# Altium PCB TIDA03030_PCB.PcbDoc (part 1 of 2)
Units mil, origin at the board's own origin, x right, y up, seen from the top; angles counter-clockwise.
Board outline 2230 x 2185 mil, 4 copper layers (Top Layer, Power, Gnd, Bottom Layer), stack 59.6 mil thick; 88 components, 48 nets, 250 pads, 119 vias.
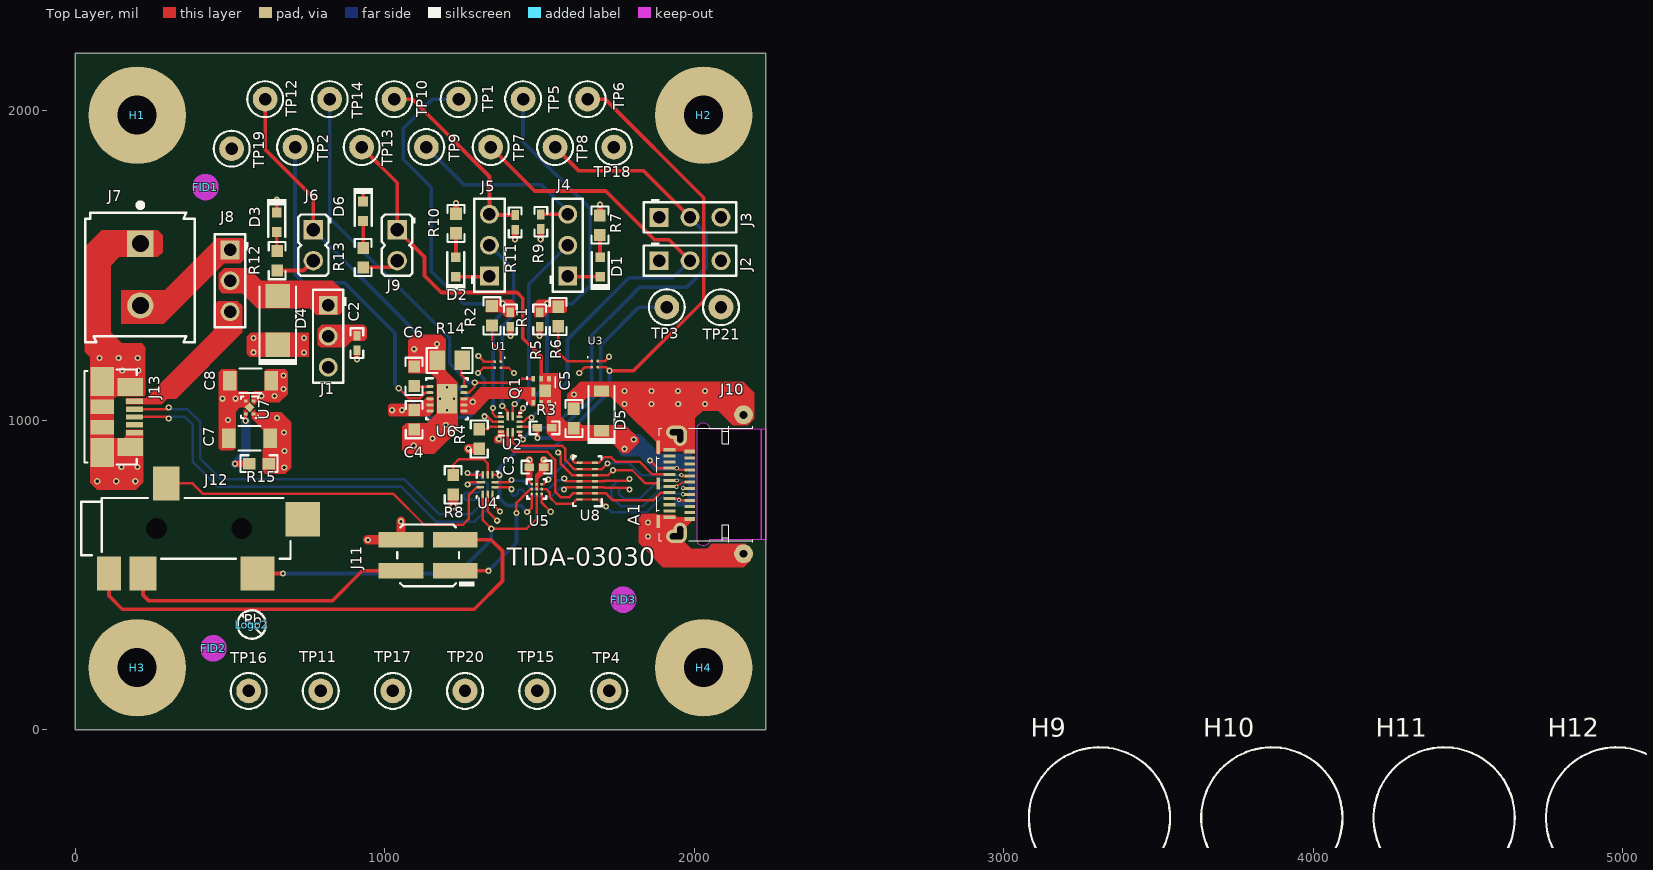
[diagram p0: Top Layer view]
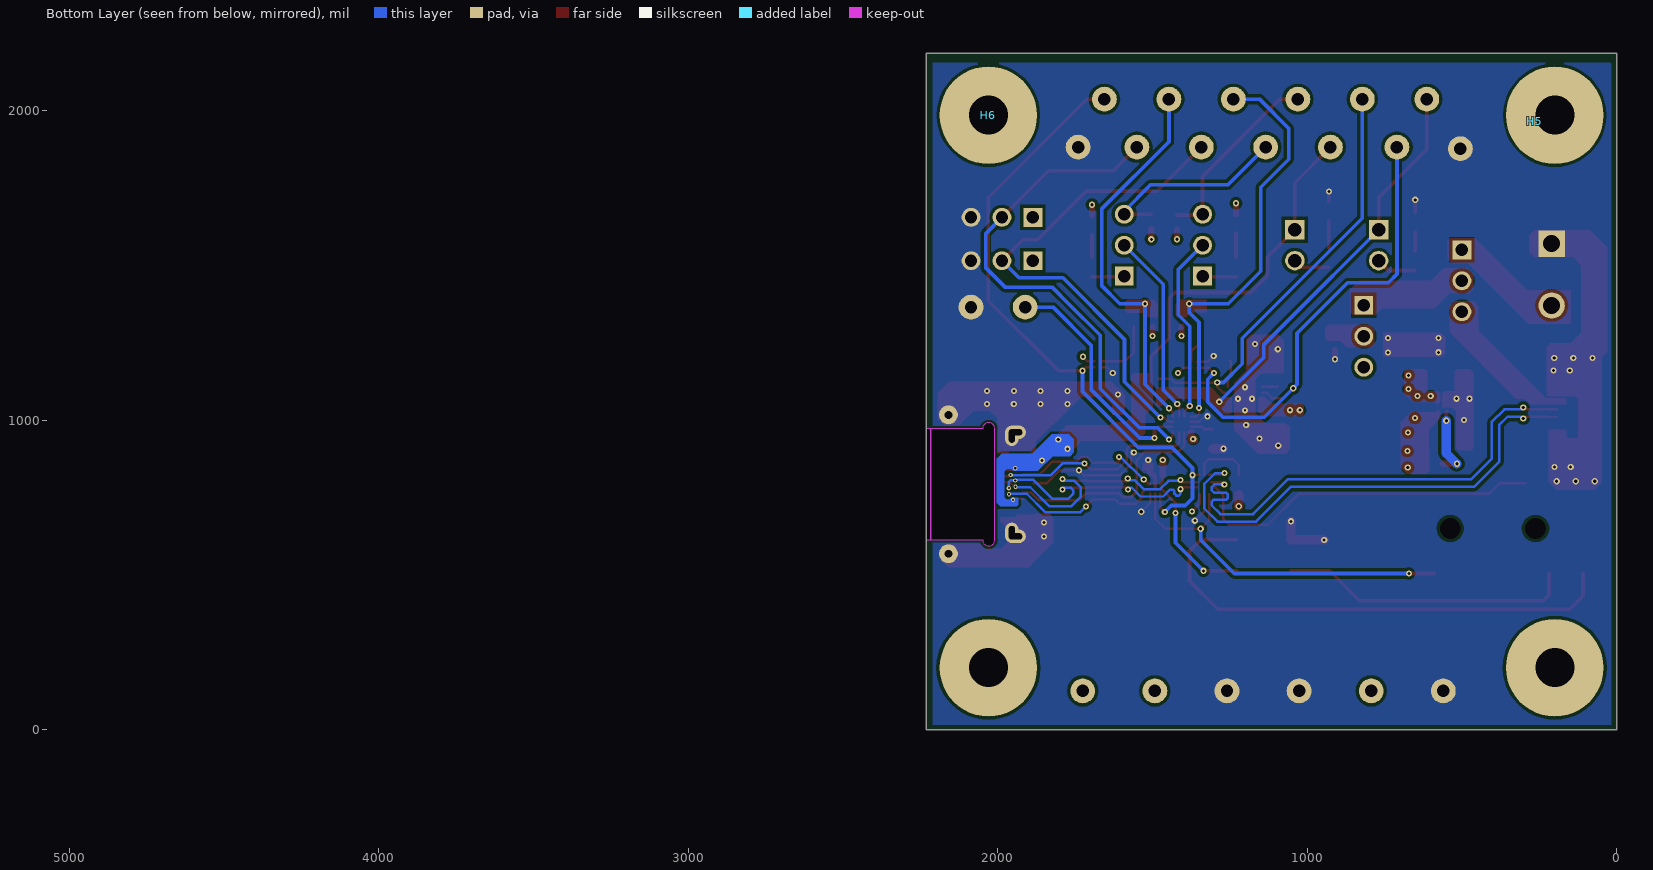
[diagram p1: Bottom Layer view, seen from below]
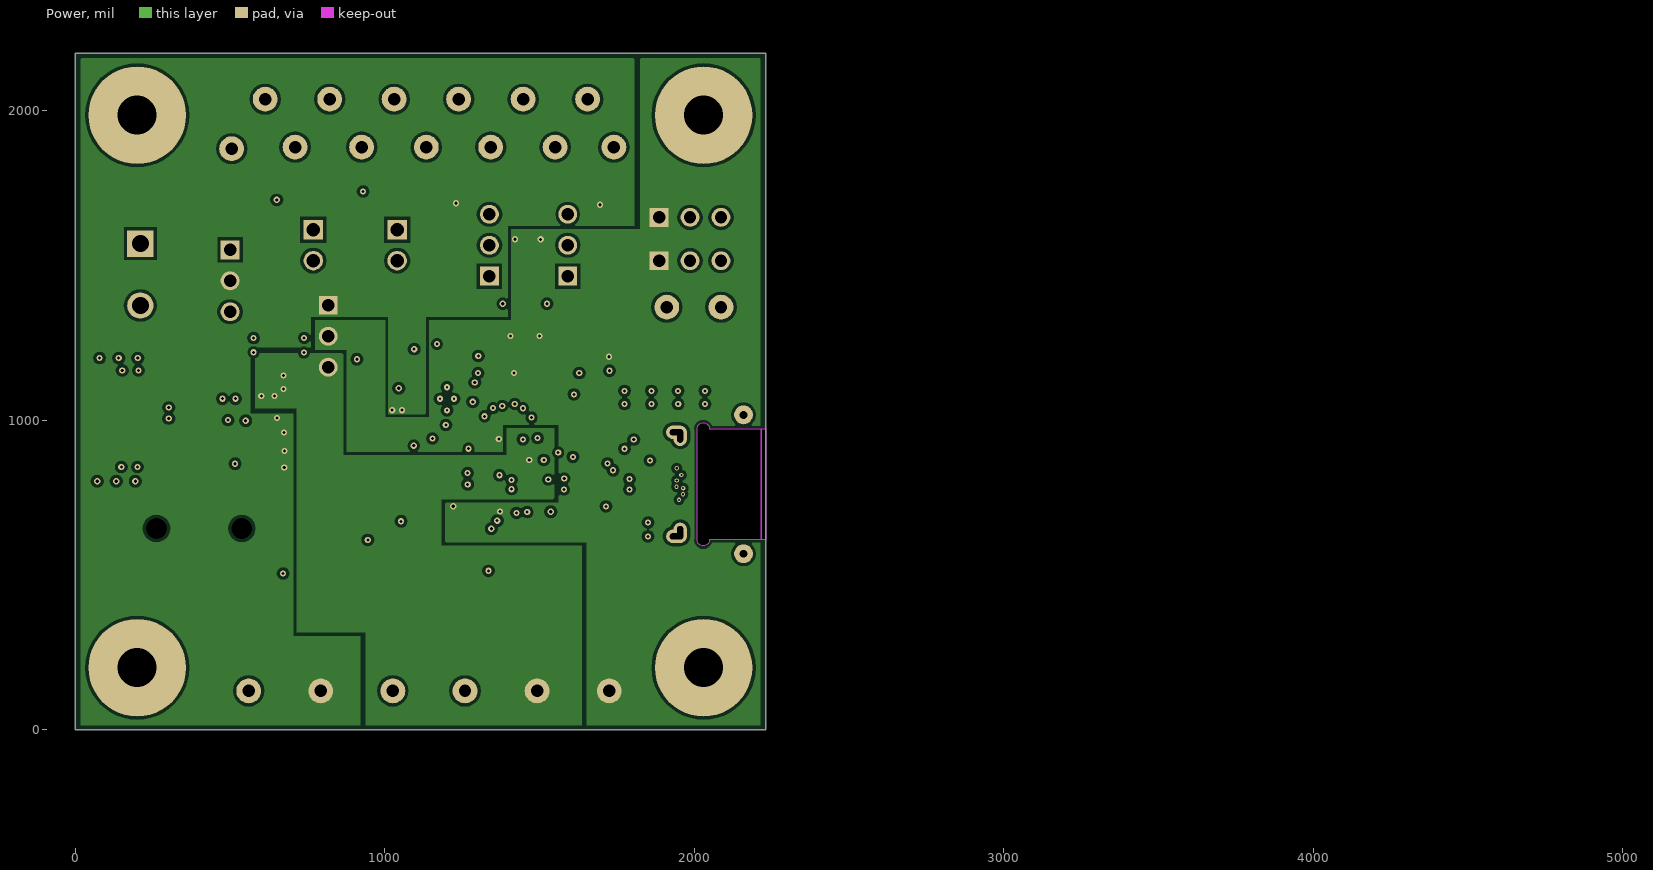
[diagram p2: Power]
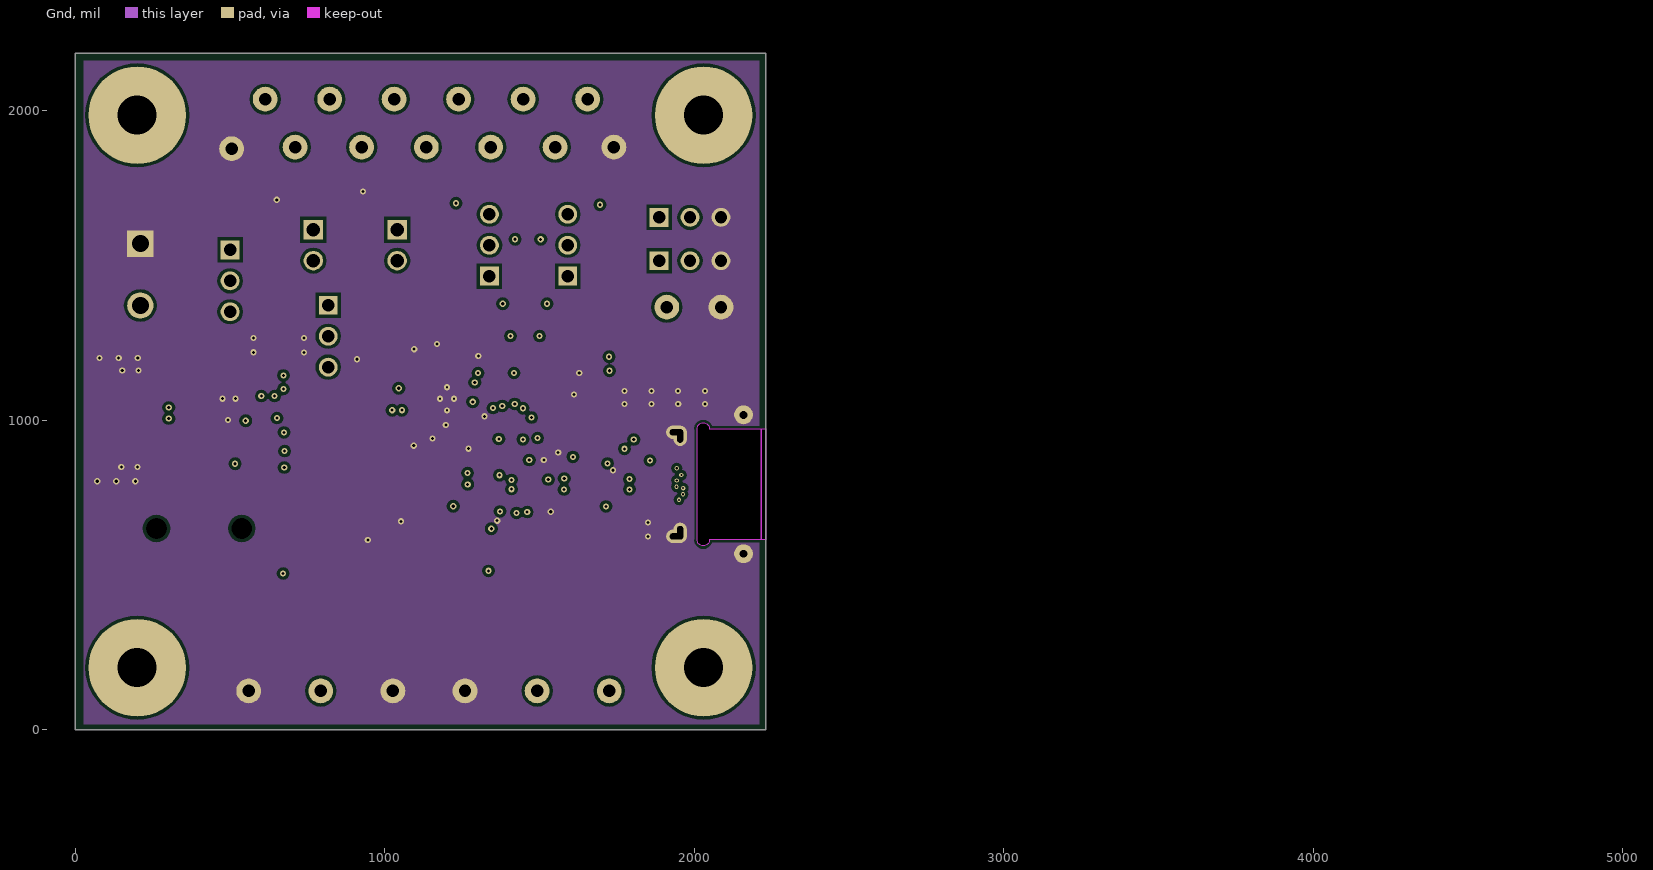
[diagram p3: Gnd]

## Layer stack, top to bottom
Top Solder: solder mask 0.7, Solder Resist, Dk 3.5
Top Layer: signal copper 1.5
Dielectric1: core 6, FR-4, Dk 4.8
Power: signal copper 1.3
Dielectric 2: core 42, Dk 4.2
Gnd: signal copper 1.3
Dielectric 3: core 6, Dk 4.2
Bottom Layer: signal copper 1.5
Bottom Solder: solder mask 0.7, Solder Resist, Dk 3.5

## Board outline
0,0 2230,0 2230,2185 0,2185
cut-out: 2215.86,971.64 2230,971.64 2230,613.38 2230,613.37 2215.86,613.37

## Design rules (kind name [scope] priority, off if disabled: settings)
AcuteAngle [All] p1: minimum=4.50000000000000E+0001 checktracksonly=FALSE
AssemblyTestPointUsage [All] p1: valid=2
Clearance Clearance_1 [withinroom('RoomDefinition_1')] p1: gap=5
Clearance Clearance_Keepouts [((IsTrack Or IsArc) And Not InPoly) And IsFree and IsKeepOut vs ((IsTrack Or IsArc) And Not InPoly) And IsFree and IsKeepOut] p2: gap=0
Clearance Clearance_Poly [InPolygon] p3: gap=10
Clearance [All] p4: gap=5
ComponentClearance ComponentClearance_MountingHoles_FiducialMarks [InComponentClass('Mounting Holes') vs InComponentClass('FiducialMark')] p1: gap=50 collisioncheckmode=3 verticalgap=10 showdistances=FALSE
ComponentClearance ComponentClearance_Shunt [InComponentClass('Header') vs InComponentClass('Shunt')] p2: gap=0 collisioncheckmode=3 verticalgap=0 showdistances=FALSE
ComponentClearance ComponentClearance_Logo [InComponentClass('Logo')] p3: gap=50 collisioncheckmode=3 verticalgap=10 showdistances=FALSE
ComponentClearance ComponentClearance_ScrewToNut [(HasFootprint('NY PMS 440 0025 PH')) vs (HasFootprint('Keystone_1902C'))] p4: gap=5 collisioncheckmode=3 verticalgap=10 showdistances=FALSE
ComponentClearance ComponentClearance_MountingHoles [InComponentClass('Mounting Holes')] p5: gap=250 collisioncheckmode=3 verticalgap=100000 showdistances=FALSE
ComponentClearance ComponentClearance_SmallPassives [HasFootprint('0201*') or HasFootprint('0402*') or HasFootprint('0508') or HasFootprint('0603*') or HasFootprint('0612') or HasFootprint('0805*') or HasFootprint('0815*') or HasFootprint('0830*') or HasFootprint('1206*') or HasFootprint('1210*') or HasFootprint('1808*') or HasFootprint('1812*') or HasFootprint('1825*') or HasFootprint('2010*') or HasFootprint('2220*') or HasFootprint('2225*') or HasFootprint('2512*') or HasFootprint('2728*') or HasFootprint('3518*') vs HasFootprint('0201*') or HasFootprint('0402*') or HasFootprint('0508') or HasFootprint('0603*') or HasFootprint('0612') or HasFootprint('0805*') or HasFootprint('0815*') or HasFootprint('0830*') or HasFootprint('1206*') or HasFootprint('1210*') or HasFootprint('1808*') or HasFootprint('1812*') or HasFootprint('1825*') or HasFootprint('2010*') or HasFootprint('2220*') or HasFootprint('2225*') or HasFootprint('2512*') or HasFootprint('2728*') or HasFootprint('3518*')] p6: gap=14.96 collisioncheckmode=3 verticalgap=10 showdistances=FALSE
ComponentClearance ComponentClearance_THtoSMT [IsThruComponent vs IsSMTComponent] p7: gap=40 collisioncheckmode=3 verticalgap=30 showdistances=FALSE
ComponentClearance ComponentClearance_THtoTH [IsThruComponent vs IsThruComponent] p8: gap=30 collisioncheckmode=3 verticalgap=30 showdistances=FALSE
ComponentClearance [All] p9: gap=30 collisioncheckmode=3 verticalgap=10 showdistances=FALSE
DiffPairsRouting [All] p1: maxlimit=16 minlimit=16 mostfreqgap=16 toplayer_minwidth=6 toplayer_maxwidth=20 toplayer_prefwidth=10 midlayer1_minwidth=6 midlayer1_maxwidth=20 midlayer1_prefwidth=10 midlayer2_minwidth=6 midlayer2_maxwidth=20 midlayer2_prefwidth=10 bottomlayer_minwidth=6 bottomlayer_maxwidth=20 bottomlayer_prefwidth=10 maxuncoupledlength=1000
FabricationTestPointUsage TestPointUsage [All] p1: valid=2 allowmultiple=FALSE
FabricationTestpoint Testpoint [All] p1: side=3 testpointundercomponent=TRUE minsize=40 maxsize=100 preferedsize=60 minholesize=0 maxholesize=40 preferedholesize=32 testpointgrid=1 allowsidetop=TRUE allowsidebottom=TRUE usegrid=TRUE gridtolerance=0.01
FanoutControl Fanout_LCC [IsLCC] p1: bgadir=Out bgaviamode=Centered fanoutstyle=Auto fanoutdirection=Alternating viagrid=1 // Fanout_LCC (Default Rule)
FanoutControl Fanout_BGA [IsBGA] p2: bgadir=Out bgaviamode=Centered fanoutstyle=Auto fanoutdirection=Alternating viagrid=1 // Fanout_BGA (Default Rule)
FanoutControl Fanout_Default [All] p4: bgadir=Out bgaviamode=Centered fanoutstyle=Auto fanoutdirection=Alternating viagrid=1 // Fanout_Default (Default Rule)
FanoutControl Fanout_Small [(CompPinCount < 5)] p5: bgadir=Out bgaviamode=Centered fanoutstyle=Auto fanoutdirection=OutThenIn viagrid=1 // Fanout_Small (Default Rule)
HoleSize [All] p1: absolutevalues=TRUE maxlimit=251 minlimit=7 maxpercent=80.000 minpercent=20.000
MinimumAnnularRing MinimumAnnularRing_ThermalPadVias [IsVia and InAnyComponent] p1: minimumring=5
MinimumAnnularRing [All] p2: minimumring=3
MinimumSolderMaskSliver MinimumSolderMaskSliver_Logo [InComponentClass('Logo') vs InComponentClass('Logo')] p1: minsoldermaskwidth=0.7
MinimumSolderMaskSliver [All] p2: minsoldermaskwidth=3.94
PlaneClearance [All] p1: clearance=10
PlaneConnect [All] p1: planeconnectstyle=Direct reliefexpansion=10 reliefentries=4 reliefconductorwidth=10 reliefairgap=10
PolygonConnect [All] p1: connectstyle=Direct reliefconductorwidth=10 reliefentries=4 polygonreliefangle="90 Angle" airgapwidth=10
RoutingVias ThermalPadVias [IsVia and InAnyComponent] p1: holewidth=7.87 width=19.68 viastyle="Through Hole" minholewidth=7.87 minwidth=19.68 maxholewidth=12.99 maxwidth=23.62
RoutingVias [All] p2: holewidth=16 width=34 viastyle="Through Hole" minholewidth=7 minwidth=14 maxholewidth=10 maxwidth=20
SilkToBoardRegionClearance [Not ((IsComment or IsDesignator) And (Hide <> 'False')) and not InRegion(1000,500,4000,800)] p1:
SilkToSilkClearance SilkToSilkClearance_Pb-FreeLogo [(HasFootprint('Pb-Free_Overlay_Medium') OR HasFootprint('Pb-Free_Overlay_Small')) vs (HasFootprint('Pb-Free_Overlay_Medium') OR HasFootprint('Pb-Free_Overlay_Small'))] p1: silktosilkclearance=0
SilkToSilkClearance [All] p2: silktosilkclearance=4
SilkToSolderMaskClearance SilkToComponentPadClearance [IsPad and InAnycomponent] p1: minsilkscreentomaskgap=5 clearancetoexposedcopper=TRUE
SilkToSolderMaskClearance "Silk to Solder Mask Opening" [All] p2: minsilkscreentomaskgap=4 clearancetoexposedcopper=FALSE
SolderMaskExpansion [All] p1: expansion=1.97
Width [All] p1: maxlimit=30 minlimit=3 preferedwidth=12 toplayer_minwidth=5 toplayer_prefwidth=8 midlayer1_minwidth=8 midlayer2_minwidth=8 minimp=50.000000 maximp=50.000000 favimp=50.000000 checkconnectedcopper=TRUE
14 further rules are at their usual default settings.

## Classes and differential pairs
component class TIDA03030_Controller&Switches: 45 C2 C3 D1 D2 J1 J2 J3 J4 J5 R1 R2 R3 R4 R5 R6 R7 R8 R9 R10 R11 TP1 TP2 TP3 TP4 TP5 TP6 TP7 TP8 TP9 TP10 U1 U2 U3 U4 U5
component class TIDA03030_Hardware: FID1 FID2 FID3 H1 H2 H3 H4 H5 H6 H9 H10 H11 H12 Logo2 Logo3 TIDA-03030
component class FiducialMark: FID1 FID2 FID3
component class Header: J6 J9 J11
component class TIDA03030_Connectors: J10 J11 J12 J13 U8
component class TIDA03030_Power: C4 C5 C6 C7 C8 D3 D4 D5 D6 J6 J7 J8 J9 Q1 R12 R13 R14 R15 TP11 TP12 TP13 TP14 TP15 TP16 TP17 TP18 TP19 TP20 TP21 U6 U7
component class "Mounting Holes": H1 H2 H3 H4
differential pair NewDifferentialPair2: +USB_D+ -USB_D-
differential pair NewDifferentialPair1: +USB_C_D- -USB_C_D+

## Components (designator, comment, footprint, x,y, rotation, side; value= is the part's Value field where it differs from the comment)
C2 "GCM155R71C104KA55D" 0402 910,1249 r270 top
C3 "GCM155R71C104KA55D" 0402 1490,848 r0 top
C4 "GCM188R71C105KA64D" 0603 1094.5,1001.57 r270 top
C5 "GCM188R71C105KA64D" 0603 1611,1005 r90 top
C6 "GRM1885C1H302JA01D" 0603 1094.5,1141.57 r90 top
C7 "C3216X7R1H105K160AB" 1206_180 562.64,941.14 r180 top
C8 "C3216X7R1H105K160AB" 1206_180 566,1127.2 r180 top
D1 "150060GS75000" WL-SMCW_GREEN 1696,1495 r90 top
D2 "150060GS75000" WL-SMCW_GREEN 1229,1495 r90 top
D3 "150060BS75000" WL-SMCW_Blue 651,1639 r270 top
D4 "SMAJ7.5CA" SMA 654,1322 r90 top
D5 "30V" SOD-123 1700,1030 r90 top
D6 "150060BS75000" WL-SMCW_Blue 929.82,1675 r270 top
FID1 "Fiducial" Fiducial10-20#1 420.35,1752.75 r0 top
FID2 "Fiducial" Fiducial10-20#2 494.31,261.44 r0 top
FID3 "Fiducial" Fiducial10-20#1 1770,420 r0 top
H1 "NY PMS 440 0025 PH" "NY PMS 440 0025 PH"#1 265,1965 r0 top
H2 "NY PMS 440 0025 PH" "NY PMS 440 0025 PH"#2 1970,2060 r0 top locked
H3 "NY PMS 440 0025 PH" "NY PMS 440 0025 PH"#3 185,175 r0 top locked
H4 "NY PMS 440 0025 PH" "NY PMS 440 0025 PH"#4 2030,200 r0 top locked
H5 "1902C" Keystone_1902C#1 265,1965 r180 bottom
H6 "1902C" Keystone_1902C#1 2030,1985 r180 bottom
H7 "1902C" Keystone_1902C#2 200,200 r90 bottom
H8 "1902C" Keystone_1902C#2 2030,200 r90 bottom
H9 "SJ-5303 (CLEAR)" Bumpon_SJ5003Transparent 3308.79,-285.01 r90 top
H10 "SJ-5303 (CLEAR)" Bumpon_SJ5003Transparent 3865.61,-285.01 r90 top
H11 "SJ-5303 (CLEAR)" Bumpon_SJ5003Transparent 4422.44,-285.01 r90 top
H12 "SJ-5303 (CLEAR)" Bumpon_SJ5003Transparent 4979.27,-285.01 r90 top
J1 "HTSW-103-09-G-S" Samtec_HTSW-103-09-x-S 817,1271 r270 top
J2 "HTSW-103-09-G-S" Samtec_HTSW-103-09-x-S 1986,1515 r0 top
J3 "HTSW-103-09-G-S" Samtec_HTSW-103-09-x-S 1986,1655 r0 top
J4 "HTSW-103-09-G-S" Samtec_HTSW-103-09-x-S 1591,1565 r90 top
J5 "HTSW-103-09-G-S" Samtec_HTSW-103-09-x-S 1338,1565 r90 top
J6 "961102-6404-AR" 3M_961102-6404-AR 768.82,1565 r270 top
J7 "282841-2" TEC_282841-2 210,1470 r270 top
J8 "HTSW-103-09-G-S" Samtec_HTSW-103-09-x-S 500,1450 r270 top
J9 "961102-6404-AR" 3M_961102-6404-AR 1039.82,1565 r270 top
J10 "20-0000016-01" Lintes_20-0000016-01 2215.86,792.51 r90 top locked
J11 "15-91-2040" Molex_15-91-2040 1140,563 r90 top
J12 "SJ-43515TS-SMT-TR" CUI_SJ-43515TS-SMT 400,650 r0 top locked
J13 "0473460001" CONN_47346-0001 30,1010 r90 top
Logo2 "Pb-Free Symbol" Pb-Free_Overlay_Small 569.93,339.45 r0 top
Q1 "30V" TRANS_NexFET_Q2 1505,1095 r270 top
R1 "CRCW0402200KFKED" 0402 1405.5,1325 r90 top
R2 "CRCW06030000Z0EA" 0603 1346.23,1336.89 r90 top
R3 "CRCW0402909KFKED" 0402 1516,975 r0 top
R4 "CRCW06030000Z0EA" 0603 1305.03,939.17 r90 top
R5 "CRCW0402200KFKED" 0402 1500,1325 r90 top
R6 "CRCW06030000Z0EA" 0603 1560,1335 r90 top
R7 "RC0603FR-07909RL" 0603 1695,1630 r90 top
R8 "CRCW06030000Z0EA" 0603 1221,791 r90 top
R9 "CRCW04024K70JNED" 0402 1504,1641 r270 top
R10 "RC0603FR-07909RL" 0603 1230,1635 r90 top
R11 "CRCW04024K70JNED" 0402 1421,1639 r270 top
R12 "CRCW0603845RFKEA" 0603 652,1515 r270 top
R13 "CRCW0603845RFKEA" 0603 929.82,1525 r270 top
R14 "CRCW080510K2FKEA" 0805_HV 1209.5,1192.57 r0 top
R15 "CRCW06030000Z0EA" 0603 593.36,859.14 r0 top
TIDA-03030 "FCC disclaimer" FCC_disclaimer 2310.5,692.08 r90 top (schematic designator Logo3)
TP1 "5116" Keystone_5116 1238.33,2037 r180 top
TP2 "5116" Keystone_5116 710,1882 r180 top
TP3 "5116" Keystone_5116 1911,1365 r0 top
TP4 "5116" Keystone_5116 1725,125 r180 top
TP5 "5116" Keystone_5116 1446.67,2037 r90 top
TP6 "5116" Keystone_5116 1655,2037 r0 top
TP7 "5116" Keystone_5116 1342,1882 r90 top
TP8 "5116" Keystone_5116 1550,1882 r90 top
TP9 "5116" Keystone_5116 1134,1882 r90 top
TP10 "5116" Keystone_5116 1030,2037 r90 top
TP11 "5117" Keystone5117 793,125 r270 top
TP12 "5117" Keystone5117 613.33,2037 r90 top
TP13 "5117" Keystone5117 925,1882 r90 top
TP14 "5117" Keystone5117 821.67,2037 r180 top
TP15 "5117" Keystone5117 1492,125 r0 top
TP16 "5001" Keystone5001 560,125 r180 top
TP17 "5001" Keystone5001 1026,125 r90 top
TP18 "5001" Keystone5001 1740,1882 r180 top
TP19 "5001" Keystone5001 505,1877 r180 top
TP20 "5001" Keystone5001 1259,125 r180 top
TP21 "5001" Keystone5001 2086,1365 r90 top
U1 "SN74LVC1G04YZVR" YZV0004ADAD 1365,1179 r270 top
U2 "TUSB320LAI" RWB0012A 1405,986.57 r90 top
U3 "SN74LVC1G04YZVR" YZV0004ADAD 1678,1181 r0 top
U4 "TS5USBA224RSWR" RSW0010A 1332,791.57 r0 top
U5 "TS3A226AEYFFR" YFF0009AEAJ 1490.67,777.2 r0 top
U6 "TPS259230DRCR" DRC0010J 1200.76,1068.86 r0 top
U7 "TLV73333PDQNR" DQN0004A 563.2,1041.14 r270 top
U8 "TPD6E05U06RVZR" RVZ0014A 1654,802.57 r180 top

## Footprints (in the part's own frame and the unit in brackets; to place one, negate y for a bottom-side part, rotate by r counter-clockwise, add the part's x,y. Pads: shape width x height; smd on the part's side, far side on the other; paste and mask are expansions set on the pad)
3M_961102-6404-AR [mm] "Header, 2.54mm, 2x1, TH"
  rect 1.6x1.6 hole 1.1: 1(-1.27,0)
  round 1.6 hole 1.1: 2(1.27,0)
  silkscreen extent -2.52,-1.25 2.52,1.5, body extent -2.52,-1.25 2.52,1.25, height 8.5
0402 [mm] "0402 from SM-752 data"
  rect 0.8x0.6 smd: 1(-0.6,0) 2(0.6,0)
  silkscreen extent -1.22,-0.52 1.22,0.52, body extent -0.55,-0.3 0.55,0.3, height 0.6
0603 [mm] "0603 from SM-752 data"
  rect 1x0.95 smd: 1(-0.8,0) 2(0.8,0)
  silkscreen extent -1.52,-0.69 1.52,0.69, body extent -0.87,-0.47 0.87,0.47, height 1
0805_HV [mil] "0805 with 30mil clearance between pads"
  rect 50x63 smd: 1(-40,0) 2(40,0)
  silkscreen extent -74,-40 74,40, body extent -43,-29 43,29, height 57
1206_180 [mm] "1206_180"
  rect 1.1x1.6 smd: 1(-1.7,0) 2(1.7,0)
  silkscreen extent -0.9,-1 0.9,1, body extent -1.75,-0.95 1.75,0.95, height 1.8
Bumpon_SJ5003Transparent [mil] "3M Hemispherical Bumpon transparent"
  round 1 on Mech3: 0(0,0)
  silkscreen extent -228,-228 228,228, body extent -217,-218 219,218, height 197
CONN_47346-0001 [mm] "MOLEX"
  rect 0.45x1.38 smd: 1(1.3,-4.105) 2(0.65,-4.105) 3(0,-4.105) 4(-0.65,-4.105) 5(-1.3,-4.105)
  rect 1.475x2.1 smd: 6(-2.462,-3.755) 11(2.463,-3.75)
  rect 2.375x1.9 smd: 7(-2.912,-1.45) 10(2.912,-1.45)
  rect 1.175x1.9 smd: 8(-0.837,-1.45) 9(0.837,-1.45)
  silkscreen extent -3.9,-4.28 3.9,0, body extent -3.99,-4.43 3.99,1, height 2.72
CUI_SJ-43515TS-SMT [mm] "3.5 mm Audio Jack Connector, Body 17 x 6 mm"
  rect 2x2.8 smd: 1(-7.4,-3.7)
  rect 2.8x2.8 smd: 2(4.8,-3.7) 5(8.5,0.75)
  rect 2.2x2.8 smd: 3(-2.7,3.7) 4(-4.6,-3.7)
  round 1 hole 1.7 unplated mask+0.35: MH1(-3.5,0) MH2(3.5,0)
  silkscreen extent -9.67,-2.5 7.5,2.5, body extent -9.7,-4.5 9.5,4.5, height 5.1
DQN0004A [mm] "SON, 0.65mm pitch"
  rect 0.25x0.31 smd paste-1 mask-0.31: 1(-0.535,0.325) 2(-0.535,-0.325) 3(0.535,-0.325) 4(0.535,0.325)
  rect 0.58x0.58 smd rot 45 paste-0.065 mask+0: 5(0,0)
  Top Layer region: -0.66,0.48 -0.2,0.48 -0.2,0.379 -0.409,0.17 -0.66,0.17
  Top Layer region: 0.66,0.48 0.2,0.48 0.2,0.379 0.409,0.17 0.66,0.17
  Top Layer region: 0.66,-0.48 0.2,-0.48 0.2,-0.379 0.409,-0.17 0.66,-0.17
  Top Layer region: -0.66,-0.48 -0.2,-0.48 -0.2,-0.379 -0.409,-0.17 -0.66,-0.17
  silkscreen extent -0.88,-0.7 0.88,0.7, body extent -0.53,-0.53 0.53,0.53, height 0.42
DRC0010J [mm] "SON, 10-Leads, Body 3x3mm, Pitch 0.5mm, Thermal Pad 2.4x1.65mm, TI Recommended"
  rrect100% 0.6x0.24 smd: 1(-1.4,1) 2(-1.4,0.5) 3(-1.4,0) 4(-1.4,-0.5) 5(-1.4,-1) 6(1.4,-1) 7(1.4,-0.5) 8(1.4,0) 9(1.4,0.5) 10(1.4,1)
  rrect6% 1.65x2.4 smd paste-0.825: 11(0,0)
  silkscreen extent -1.7,-1.7 1.7,1.7, body extent -1.5,-1.5 1.5,1.5, height 0.77
FCC_disclaimer [mil]
Fiducial10-20#1 [mm]
  round 1 smd mask+0.5: 1(0,0)
  Top Layer keep-out circle w1.178: c0,0 r0.5
Fiducial10-20#2 [mm]
  round 1 smd mask+0.5: 1(-1.227,0.03)
  Top Layer keep-out circle w1.178: c-1.227,0.03 r0.5
Keystone5001 [mil] "For Keystone 500x miniature loop terminals"
  round 80 hole 40: 1(0,0)
  silkscreen extent -58,-58 58,58, body extent -49,-49 49,49, height 182
Keystone5117 [mil] "For Keystone 500x miniature loop terminals"
  round 80 hole 40: 1(0,0)
  silkscreen extent -58,-58 58,58, body extent -49,-49 49,49, height 182
Keystone_1902C#1 [mil] "Hex Standoff, 4-40 threaded, nylon"
  body extent -1910,-106 -1620,146, height 501
Keystone_1902C#2 [mil] "Hex Standoff, 4-40 threaded, nylon"
  round 1 on Mech4: 0(0,0)
  body extent -145,-126 146,126, height 501
Keystone_5116 [mil] "For Keystone 500x miniature loop terminals"
  round 80 hole 40: 1(0,0)
  silkscreen extent -58,-58 58,58, body extent -50,-49 50,51, height 183
Lintes_20-0000016-01 [mm] "Connector, Receptacle, USB Type C, SMT"
  rect 1.1x0.3 smd: 1(3.05,8.44) 3(-3.05,8.44)
  rect 1x0.3 smd: 2(0.07,8.44)
  rect 0.3x0.95 smd: A1(-2.7,7.525) A12(2.85,7.525)
  rect 0.25x0.95 smd: A2(-2.175,7.525) A3(-1.675,7.525) A4(-1.175,7.525) A5(-0.675,7.525) A6(-0.175,7.525) A7(0.325,7.525) A8(0.825,7.525) A9(1.325,7.525) A10(1.825,7.525) A11(2.325,7.525)
  rect 0.3x0.85 smd: B1(2.7,5.875) B12(-2.85,5.875)
  rect 0.25x0.85 smd: B2(2.175,5.875) B3(1.675,5.875) B4(1.175,5.875) B5(0.675,5.875) B6(0.175,5.875) B7(-0.325,5.875) B8(-0.825,5.875) B9(-1.325,5.875) B10(-1.825,5.875) B11(-2.325,5.875)
  oval 1.1x1.7 hole 0.5 slot 1.1 at 90 deg: H1(4.27,6.95) H3(-4.27,6.95)
  oval 1.65x1.1 hole 0.5 slot 1.095 at 0 deg: H2(3.97,6.65) H4(-3.97,6.65)
  round 1.55 hole 0.65: H5(5.7,1.45) H6(-5.7,1.45)
  Keep-Out Layer board cut-out: -4.55,0 -4.55,4.25 -4.767,4.3 -4.941,4.438 -5.037,4.639 -5.037,4.861 -4.941,5.062 -4.767,5.2 -4.55,5.25 -4.55,5.25 -4.55,5.25 4.55,5.25 4.55,5.25 4.767,5.2 4.941,5.062 5.037,4.861 5.037,4.639 4.941,4.438 4.767,4.3 4.55,4.25 4.55,4.25 4.55,0
  silkscreen extent -4.77,0.68 4.77,8.58, body extent -5.8,-1.56 5.8,8.59, height 2.44
Molex_15-91-2040 [mil] "Molex"
  rect 50x144.88 smd: 1(-50,-87.5) 2(-50,87.5) 3(50,-87.5) 4(50,87.5)
  silkscreen extent -100,-150 100,100, body extent -100,-137 100,138, height 380
"NY PMS 440 0025 PH"#1 [mm] "4-40 nylon screw and mounting hole"
  round 8 hole 3.2: 1(-1.651,0.508)
  body extent -4.95,-2.79 1.65,3.81, height 2.69
"NY PMS 440 0025 PH"#2 [mm] "4-40 nylon screw and mounting hole"
  round 8 hole 3.2: 1(1.524,-1.905)
  body extent -1.65,-4.95 4.95,1.65, height 2.69
"NY PMS 440 0025 PH"#3 [mm] "4-40 nylon screw and mounting hole"
  round 8 hole 3.2: 1(0.381,0.635)
  body extent -2.79,-2.54 3.8,4.06, height 2.69
"NY PMS 440 0025 PH"#4 [mm] "4-40 nylon screw and mounting hole"
  round 8 hole 3.2: 1(0,0)
  body extent -3.3,-3.3 3.3,3.3, height 2.69
Pb-Free_Overlay_Small [mil]
  silkscreen extent -46,-46 46,46
RSW0010A [mm] "QFN, 10-Leads, Body 1.8x1.4 mm, Pitch 0.4mm, TI Recommended"
  rrect50% 0.7x0.2 smd: 1(-0.55,0.2)
  rrect50% 0.6x0.2 smd: 2(-0.6,-0.2) 6(0.6,-0.2) 7(0.6,0.2)
  rrect50% 0.2x0.6 smd: 3(-0.4,-0.8) 4(0,-0.8) 5(0.4,-0.8) 8(0.4,0.8) 9(0,0.8) 10(-0.4,0.8)
  silkscreen extent -0.88,-1.08 0.88,1.08, body extent -0.7,-0.9 0.7,0.9, height 0.56
RVZ0014A [mm] "SON, 14-Leads, Body 3.5x1.35mm, Pitch 0.5mm"
  rrect50% 0.5x0.2 smd: 1(-0.625,1.5) 2(-0.625,1) 3(-0.625,0.5) 4(-0.625,0) 5(-0.625,-0.5) 6(-0.625,-1) 7(-0.625,-1.5) 8(0.625,-1.5) 9(0.625,-1) 10(0.625,-0.5) 11(0.625,0) 12(0.625,0.5) 13(0.625,1) 14(0.625,1.5)
  silkscreen extent -1.18,-2.05 1.18,2.05, body extent -0.72,-1.8 0.72,1.8, height 0.55
RWB0012A [mm] "QFN, 12-Leads, Body 1.6x1.6mm, Pitch 0.4mm"
  rrect57% 0.7x0.2 smd paste-0.1: 1(-0.65,0.2) 2(-0.65,-0.2) 7(0.65,-0.2) 8(0.65,0.2)
  rrect57% 0.67x0.2 on Top Paste: 1P(-0.65,0.2) 2P(-0.65,-0.2) 7P(0.65,-0.2) 8P(0.65,0.2)
  rrect57% 0.2x0.5 smd: 3(-0.6,-0.75) 4(-0.2,-0.75) 5(0.2,-0.75) 6(0.6,-0.75) 9(0.6,0.75) 10(0.2,0.75) 11(-0.2,0.75) 12(-0.6,0.75)
  silkscreen extent -0.92,-0.91 0.92,0.91, body extent -0.82,-0.82 0.82,0.82, height 0.41
Samtec_HTSW-103-09-x-S [mm] "Header, 3x1, 2.54mm, TH"
  rect 1.55x1.55 hole 1.02: 1(-2.54,0)
  round 1.55 hole 1.02: 2(0,0) 3(2.54,0)
  silkscreen extent -3.81,-1.24 3.81,1.5, body extent -3.81,-1.24 3.81,1.24, height 8.38
SMA [mm] "Molded Diode, 2-Leads, Body 4.3x2.6mm, IPC Medium Density, based on OnSemi component dimensions and land pattern"
  rect 2x2 smd: 1(-2,0) 2(2,0)
  silkscreen extent -3.66,-1.57 2.79,1.57, body extent -2.6,-1.3 2.6,1.3, height 2.42
SOD-123 [mm] "On Semi recommended land pattern"
  rect 0.915x1.22 smd: 1(-1.637,0) 2(1.637,0)
  silkscreen extent -2.74,-1.17 2.03,1.17, body extent -1.93,-0.9 1.93,0.9, height 1.35
TEC_282841-2 [mm] "TE Connectivity"
  rect 2.15x2.15 hole 1.4: 1(-2.54,0)
  round 2.15 hole 1.4: 2(2.54,0)
  silkscreen extent -5.9,-4.52 5.55,4.47, body extent -5.08,-4.52 5.58,4.48, height 15.2
TRANS_NexFET_Q2 [mm] "TI recommended land pattern M0167-01"
  rrect33% 0.45x0.3 smd: 1(-0.975,0.65) 2(-0.975,0) 3(-0.975,-0.65) 4(0.975,-0.65) 5(0.975,0) 6(0.975,0.65)
  rrect33% 0.75x0.3 smd paste-0.025: 7(0.095,-0.65)
  rrect11% 1x0.95 smd paste-0.025: 8(0,0.325)
  silkscreen extent -1.15,-1.15 1.15,1.15, body extent -1,-1 1,1, height 0.85
WL-SMCW_Blue [mm] "SMD, 2-Leads, Body 1.6x0.8mm"
  rect 0.8x0.8 smd: 1(-0.8,0) 2(0.8,0)
  silkscreen extent -1.9,-0.8 1.2,0.8, body extent -0.85,-0.45 0.85,0.45, height 0.8
WL-SMCW_GREEN [mm] "WURTH"
  rect 0.8x0.8 smd: 1(-0.8,0) 2(0.8,0)
  silkscreen extent -1.9,-0.8 1.2,0.8, body extent -0.85,-0.45 0.85,0.45, height 0.8
YFF0009AEAJ [mm] "BGA, 9-Balls, Body 1.256x1.356mm, Pitch 0.4mm"
  round 0.23 smd paste-0.13 mask+0.038: A1(-0.4,0.4) A2(0,0.4) A3(0.4,0.4) B1(-0.4,0) B2(0,0) B3(0.4,0) C1(-0.4,-0.4) C2(0,-0.4) C3(0.4,-0.4)
  silkscreen extent -0.81,-0.79 0.79,0.82, body extent -0.64,-0.69 0.64,0.69, height 0.63
YZV0004ADAD [mm] "BGA, 4-Leads, Pitch 0.5mm"
  round 0.23 smd mask+0.04: A1(-0.25,0.25) A2(0.25,0.25) B1(-0.25,-0.25) B2(0.25,-0.25)
  silkscreen extent -0.63,0.51 -0.53,0.61, body extent -0.46,-0.46 0.46,0.46, height 0.56

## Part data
C2 C3: "CAP, CERM, 0.1 µF, 16 V, +/- 10%, X7R, 0402"
C4 C5: "CAP, CERM, 1 µF, 16 V, +/- 10%, X7R, AEC-Q200 Grade 1, 0603"
C6: "CAP, CERM, 3000 pF, 50 V, +/- 5%, C0G/NP0, 0603"
C7 C8: "CAP, CERM, 1 µF, 50 V, +/- 10%, X7R, 1206"
D1 D2: "LED, Green, SMD"
D3 D6: "LED, Blue, SMD"
D4: "Diode, TVS, Bi, 7.5 V, 400 W, SMA"
D5: library part MBR130T1G, "Diode, Schottky, 30 V, 1 A, SOD-123"
FID1 FID2 FID3: "Fiducial mark.  There is nothing to buy or mount."
H1 H2 H3 H4: "Machine Screw, Round, #4-40 x 1/4, Nylon, Philips panhead"
H5 H6 H7 H8: "Standoff, Hex, 0.5\"L #4-40 Nylon"
H9 H10 H11 H12: "Bumpon, Hemisphere, 0.44 X 0.20, Clear"
J1 J2 J3 J4 J5 J8: "Header, 100mil, 3x1, Gold, TH"
J6 J9: "Header, 2.54mm, 2x1, TH"
J7: "Terminal Block, 2x1, 5.08mm, TH"
J10: "Connector, Receptacle, USB Type C, R/A, SMT"
J11: "Header, 100mil, 2x2, Tin, SMT"
J12: "Audio Jack, 3.5mm, Stereo, R/A, SMT"
J13: "Connector, Receptacle, Micro-USB Type B, R/A, Bottom Mount SMT"
Logo2: library part Pb-Free
Q1: library part CSD17571Q2, "MOSFET, N-CH, 30 V, 7.6 A, SON 2x2mm"
R1 R5: "RES, 200 k, 1%, 0.063 W, 0402"
R2 R4 R6 R8 R15: "RES, 0, 5%, 0.1 W, 0603"
R3: "RES, 909 k, 1%, 0.063 W, 0402"
R7 R10: "RES, 909, 1%, 0.1 W, 0603"
R9 R11: "RES, 4.7 k, 5%, 0.063 W, 0402"
R12 R13: "RES, 845, 1%, 0.1 W, 0603"
R14: "RES, 10.2 k, 1%, 0.125 W, 0805"
TIDA-03030: library part FCC_disclaimer, "FCC_disclaimer"
TP1 TP2 TP3 TP4 TP5 TP6 TP7 TP8 TP9 TP10: "Test Point, Miniature, Green, TH"
TP11 TP12 TP13 TP14 TP15: "Test Point, Miniature, Blue, TH"
TP16 TP17 TP18 TP19 TP20 TP21: "Test Point, Miniature, Black, TH"
U1 U3: "Single Inverter Gate, YZV0004ADAD"
U2: library part TUSB320IRWBR, "USB Type-C Configuration Channel Logic and Port Control, RWB0012A"
U4: "USB 2.0 High-Speed (480Mbps) and Audio Switches with Negative Signal Capability,3 / 4 ohm RON, -40 to 85 degC, 10-Pin UQFN (RSW), Green (RoHS & no Sb/Br)"
U5: "Autonomous Audio Headset Switch with Reduced GND Switch RON and FM Capability,YFF0009AEAJ"
U6: "12-V eFuse with Over Voltage Protection and Blocking FET Control, DRC0010J"
U7: "Capacitor-Free, 300-mA, Low-Dropout Regulator, DQN0004A"
U8: "1, 4, 6 Channel ESD Protection Device for Super-Speed (up to 6 Gbps) Interface, RVZ0014A"

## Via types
v1: diameter 20, hole 10, Top Layer to Bottom Layer, 108 vias
v2: diameter 14, hole 7, Top Layer to Bottom Layer, 7 vias
v3: diameter 19.68, hole 7.87, Top Layer to Bottom Layer, 4 vias

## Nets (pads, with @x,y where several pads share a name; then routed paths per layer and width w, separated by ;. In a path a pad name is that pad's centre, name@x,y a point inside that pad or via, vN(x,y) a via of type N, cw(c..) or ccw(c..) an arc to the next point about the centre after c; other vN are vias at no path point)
3V3: C3.1 C8.1 J1.3 TP15.1 U5.A1 U7.1 | length 82.1
  Top Layer w8: C3.1@1465.63,848.75 C3.1@1466.38,848 ; 1466.38,819.2 1466.38,801.5 U5.A1@1474.92,792.95
  Top Layer w20: 1466.38,819.2 C3.1@1466.38,848
  Top Layer w25: C3.1@1465.63,848.75 1466.45,849.57 v1(1466.45,870.83)
  other v1: 601,1077.43 643.73,1077.43 672.27,1100.49 672.27,1144.27
5V0: C4.1 C7.1 D4.2 J1.1 J8.2 R7.2 R10.2 R15.2 TP11.1 U6.3 U6.4 U6.5 U7.4 | length 68.3
  Top Layer w20: R10.2@1230,1666.5 v1(1230,1700.66) ; R7.2@1695,1661.5 v1(1695,1695.66)
  other v1: 675.03,846.68 676.22,899.88 674.16,960.39 651.53,1006.49 1023.7,1032 1055,1032
ADDR: J2.2 TP7.1 U2.5 | length 1643.2
  Top Layer w8: U2.5@1434.53,994.44 1448.3,994.44 1461.79,1007.93 v1(1474.22,1007.93)
  Top Layer w12: TP7.1@1342,1882 1484,1740 1714,1740 1871,1583 1918,1583 J2.2@1986,1515
  Bottom Layer w12: v1(1474.22,1007.93) 1590,1123.71 1590,1260.35 1789.22,1459.56 1930.56,1459.56 J2.2@1986,1515
AUDIO_EN: TP6.1 U3.B2 U4.8 U5.C1 | length 2098.5
  Top Layer w8: U4.8@1347.75,823.06 1369.16,823.06 v1(1370.18,822.04) ; v1(1459.8,702.95) 1474.92,718.07 U5.C1@1474.92,761.46 ; U3.B2@1687.84,1171.16 1714.18,1171.16 v1(1725.92,1159.42)
  Top Layer w12: TP6.1@1655,2037 1711,2037 2030,1718 2030,1385.93 1803.49,1159.42 v1(1725.92,1159.42)
  Bottom Layer w12: v1(1459.8,702.95) 1438.85,723.91 1394,723.91 1370.18,747.72 v1(1370.18,822.04) 1370.18,845.18 1436.67,911.67 1545.34,911.67 1725.92,1092.24 v1(1725.92,1159.42)
AUX_L: J12.2 U4.3 U5.C2 | length 1198.8
  Top Layer w8: U4.3@1316.25,760.07 1316.25,676.75 v1(1344,649) 1458.3,649 1490.67,681.37 U5.C2@1490.67,761.46
  Top Layer w12: J12.2@588.98,504.33 v1(671.31,504.33)
  Bottom Layer w12: v1(671.31,504.33) 1235.33,504.33 1344,613 v1(1344,649)
AUX_MIC: J11.1 U5.B1 | length 432.5
  Top Layer w8: v1(1425.47,700.17) 1425.26,700.38 1425.26,732.34 1470.12,777.2 U5.B1@1474.92,777.2
  Top Layer w12: J11.1@1227.5,513 v1(1334.81,513)
  Bottom Layer w12: v1(1334.81,513) 1425.47,603.66 v1(1425.47,700.17)
AUX_R: J12.3 U4.2 | length 1165.3
  Top Layer w8: J12.3@293.7,795.67 379.08,795.67 412.98,761.77 1027.53,761.77 1127.3,662 1252.59,662 1270.58,679.99 1270.58,756.48 1297.79,783.69 U4.2@1308.38,783.69
GND: C2.2 C3.2 C4.2 C5.2 C6.2 C7.2 C8.2 D3.1 D4.1 D5.2 D6.1 J2.3 J3.3 J7.1 J10.1 J10.2 J10.3 J10.A1 J10.A12 J10.B1 J10.B12 J10.H1 J10.H2 J10.H3 J10.H4 J10.H5 J10.H6 J11.4 J13.5 J13.6 J13.7 J13.8 J13.9 J13.10 J13.11 R4.1 R14.1 TP16.1 TP17.1 TP18.1 TP19.1 TP20.1 TP21.1 U1.B1 U2.10 U3.B1 U4.4 U5.A2 U5.B2 U5.C3 U6.11 U7.2 U7.5 U8.5 U8.10 | length 1140.4
  Top Layer w8: v1(1302,1207) 1320.16,1188.84 U1.B1@1355.16,1188.84 ; v1(1322.22,1012.25) 1331.66,1012.23 1349.45,994.44 U2.10@1375.47,994.44 ; U4.4@1332,760.07 1332,706 v1(1363,675) ; U5.B2@1490.67,777.2 U5.A2@1490.67,792.95 1490.67,808.31 1513.62,831.26 C3.2@1513.62,848 ; U5.C3@1506.42,761.46 1506.42,733.5 v1(1536.11,703.8) ; v1(1559.99,895.2) 1568.65,886.54 1568.65,857.67 1604.07,822.25 U8.10@1629.39,822.25 U8.5@1678.61,822.25 1721.78,822.25 v1(1737.59,838.07) 1799.45,838.07 1842.26,795.26 J10.2@1883.58,795.26 ; v1(1628,1152) 1647.16,1171.16 U3.B1@1668.16,1171.16
  Top Layer w12: v1(650.88,1711.63) 651,1711.51 D3.1@651,1670.5 ; v1(909.68,1196.74) v1@910,1197.05 ; D6.1@929.82,1706.5 v1(929.82,1738.44)
  Top Layer w20: v1@910,1197.05 C2.2@910,1225.38
  Top Layer w25: C3.2@1513.62,848 v1(1513.62,871.38)
  Top Layer w30: v1(945,613) J11.4@1052.5,613 v1(1052.5,673.05) ; v1(1270.02,907.67) R4.1@1305.03,907.67
  other v1: 1850.03,624.12 1850.59,669.29 70.75,802.51 132.32,802.51 193.89,802.51 148.64,848.5 200.75,848.5 1093.47,917.31 1153.77,940.5 1197.09,984.25 493.33,999.93 1774.5,1051.84 1861.07,1051.84 1947.64,1051.84 2034.21,1051.84 475.34,1069.14 517.4,1069.14 1611,1083 1774.47,1094.47 1861.04,1094.47 1947.61,1094.47 2034.17,1094.47 151.79,1160.3 203.9,1160.3 78.61,1200.5 140.18,1200.5 201.74,1200.5 738.44,1218.23 576,1219 1094.8,1229.19 1168.43,1245.64 576,1265 739.33,1265.65
  other v3: 1200.76,1031.46 1178.12,1068.86 1223.4,1068.86 1200.76,1106.26
NetC6_1: C6.1 U6.1 | length 51.9
  Top Layer w8: C6.1@1094.5,1110.07 1096.34,1108.23 U6.1@1145.64,1108.23
NetD1_1: D1.1 J4.1 | length 105.6
  Top Layer w12: J4.1@1591,1465 1592.5,1463.5 D1.1@1696,1463.5
NetD1_2: D1.2 R7.1 | length 72.4
  Top Layer w12: R7.1@1695,1598.5 1695,1527.5 D1.2@1696,1526.5
NetD2_1: D2.1 J5.1 | length 109.6
  Top Layer w12: D2.1@1229,1463.5 1336.5,1463.5 J5.1@1338,1465
NetD2_2: D2.2 R10.1 | length 77.4
  Top Layer w12: D2.2@1229,1526.5 1230,1527.5 R10.1@1230,1603.5
NetD3_2: D3.2 R12.1 | length 61.4
  Top Layer w12: D3.2@651,1607.5 651,1547.5 R12.1@652,1546.5
NetD6_2: D6.2 R13.1 | length 87
  Top Layer w12: R13.1@929.82,1556.5 D6.2@929.82,1643.5
NetJ4_3: J4.3 R9.1 TP9.1 | length 639.9
  Top Layer w12: R9.1@1504,1664.62 1590.62,1664.62 J4.3@1591,1665
  Bottom Layer w12: TP9.1@1134,1882 1256,1760 1506,1760 1591,1675 J4.3@1591,1665
NetJ5_3: J5.3 R11.1 TP10.1 | length 617.7
  Top Layer w12: TP10.1@1030,2037 1088.34,2037 1338,1787.34 J5.3@1338,1665 1340.38,1662.62 R11.1@1421,1662.62
NetJ6_1: J6.1 Q1.4 Q1.7 TP12.1 U6.6 U6.7 U6.8 | length 1255.8
  Top Layer w12: TP12.1@613.33,2037 613.33,1874.67 768.82,1719.18 J6.1@768.82,1615
  Bottom Layer w12: J6.1@768.82,1615 1061.96,1321.85 1139.88,1243.94 1139.88,1203.12 v1(1284,1059)
NetJ6_2: J6.2 R12.2 | length 129.9
  Top Layer w12: R12.2@652,1483.5 737.32,1483.5 J6.2@768.82,1515
NetJ7_2: J7.2 J8.1
NetJ9_2: J9.2 R13.2 | length 118.9
  Top Layer w12: R13.2@929.82,1493.5 1018.32,1493.5 J9.2@1039.82,1515
NetJ11_2: J11.2 J12.4 | length 950.9
  Top Layer w12: J12.4@218.9,504.33 218.9,435.1 238,416 830.2,416 927.2,513 J11.2@1052.5,513
NetJ11_3: J11.3 J12.1 | length 1663.5
  Top Layer w12: J12.1@108.66,504.33 108.66,432.34 152,389 1288.85,389 1380.18,480.33 1380.18,576.82 1344,613 J11.3@1227.5,613
NetQ1_3: Q1.3 TP14.1 U6.9 | length 1372
  Top Layer w8: U6.9@1255.88,1088.55 1271.94,1088.55 1290.56,1107.16 v1(1290.56,1121.36) 1428.36,1121.36 1440.39,1133.39 Q1.3@1479.41,1133.39
  Bottom Layer w12: TP14.1@821.67,2037 821.67,1652.33 1209.71,1264.29 1209.71,1182.24 1270.59,1121.36 v1(1290.56,1121.36)
NetR1_2: R1.2 R2.2 TP1.1 U2.9 | length 1391.3
  Top Layer w8: v1(1349.66,1038.73) 1348.49,1037.56 1348.49,1021.31 1359.61,1010.19 U2.9@1375.47,1010.19
  Bottom Layer w12: TP1.1@1238.33,2037 1154,2037 1059.43,1942.43 1059.43,1842.57 1150,1752 1150,1481 1255,1376 v1(1381,1376) 1381,1347.23 1349.66,1315.89 v1(1349.66,1038.73)
NetR2_1: R2.1 U1.A1 | length 128.4
  Top Layer w8: R2.1@1346.23,1305.39 1346.23,1249.77 1374.84,1221.16 U1.A1@1374.84,1188.84
NetR3_1: R3.1 TP3.1 U2.4 | length 765.7
  Top Layer w8: U2.4@1434.53,978.69 1482.69,978.69 R3.1@1493.35,968.03
  Top Layer w12: v1(1493.35,941.93) R3.1@1493.35,968.03
  Bottom Layer w12: v1(1493.35,941.93) 1540.72,941.93 1698,1099.2 1698,1241.67 1821.33,1365 TP3.1@1911,1365
NetR4_2: R4.2 U2.11 | length 73.8
  Top Layer w8: R4.2@1305.03,970.67 1332.35,970.67 1340.37,978.69 U2.11@1375.47,978.69
NetR5_2: R5.2 R6.2 TP5.1 U2.6 | length 1259.4
  Top Layer w8: U2.6@1434.53,1010.19 1434.53,1026.5 v1(1446.3,1038.27)
  Bottom Layer w12: v1(1446.3,1038.27) 1524,1115.97 v1(1524,1376) 1605.19,1376 1664,1434.81 1664,1682 1446.67,1899.33 TP5.1@1446.67,2037
NetR6_1: R6.1 U3.A1 | length 204.3
  Top Layer w8: R6.1@1560,1303.5 1560,1219 1588.16,1190.84 U3.A1@1668.16,1190.84
NetR8_2: R8.2 U4.9 | length 195.1
  Top Layer w8: R8.2@1221,822.5 1221,855.9 1239.15,874.05 1318.68,874.05 1332,860.73 U4.9@1332,823.06
NetR14_2: R14.2 U6.10 | length 89
  Top Layer w8: R14.2@1249.5,1192.57 1247,1190.07 1247,1146 1255.88,1137.12 U6.10@1255.88,1108.23
NetR15_1: R15.1 U7.3 | length 220.5
  Top Layer w10: v1(550.41,997.82) U7.3@550.41,1020.07
  Top Layer w20: v1(516.37,859.14) R15.1@561.87,859.14
  Bottom Layer w30: v1(516.37,859.14) 550.41,893.18 v1(550.41,997.82)
PORT: J3.2 TP8.1 U2.3 | length 1667.8
  Top Layer w8: U2.3@1434.53,962.94 1434.53,948.98 v1(1445.87,937.64)
  Top Layer w12: TP8.1@1550,1882 1626,1806 1835,1806 J3.2@1986,1655
  Bottom Layer w12: v1(1445.87,937.64) 1483.23,975 1542,975 1668.64,1101.64 1668.64,1273.95 1769.04,1374.35 1824.27,1429.58 1976.58,1429.58 2038,1491 2038,1603 J3.2@1986,1655
PWR_EN: TP2.1 U1.B2 U6.2 | length 1614.1
  Top Layer w8: v1(1045,1103) 1077,1071 1114,1071 1131.55,1088.55 U6.2@1145.64,1088.55 ; v1(1301,1152) 1318.16,1169.16 U1.B2@1355.16,1169.16
  Bottom Layer w12: TP2.1@710,1882 710,1472.13 738.24,1443.89 869.32,1443.89 1032.49,1280.72 1032.49,1115.51 v1(1045,1103) 1138.44,1009.56 1272.23,1009.56 1321.3,1058.63 1321.3,1131.7 v1(1301,1152)
SCL/OUT2: J5.2 U2.8 | length 610.2
  Top Layer w8: v1(1379.2,1045.8) 1381.13,1045.8 1383.81,1043.12 1382.8,1042.11 1397.13,1027.78 U2.8@1397.13,1012.16
  Bottom Layer w12: J5.2@1338,1565 1416.52,1486.48 1416.52,1340.53 1379.2,1303.21 v1(1379.2,1045.8)
SDA/OUT1: J4.2 U2.7 | length 626.6
  Top Layer w8: U2.7@1412.87,1012.16 1412.87,1045.37 v1(1419.71,1052.21)
  Bottom Layer w12: v1(1419.71,1052.21) 1465,1097.5 1465,1439 J4.2@1591,1565
USB_C_CC1: J10.A5 U2.1 U8.2 U8.13 | length 721.2
  Top Layer w8: U2.1@1397.13,960.97 1397.13,916.93 1417.03,897.03 1524.97,897.03 1550.3,871.7 1550.3,768.87 1568.8,750.37 1594.45,750.37 1607.28,763.2 U8.13@1629.39,763.2 U8.2@1678.61,763.2 1714.64,763.2 1737.53,740.31 1866.11,740.31 1891.74,765.93 J10.A5@1919.6,765.93
USB_C_CC2: J10.B5 U2.2 U8.6 U8.9 | length 686.1
  Top Layer w8: U2.2@1412.87,960.97 1412.87,927.56 1422.79,917.64 1571.81,917.64 1583.34,906.11 1583.34,870.15 1611.56,841.94 U8.9@1629.39,841.94 U8.6@1678.61,841.94 1701.46,841.94 v1(1719.53,860.01) ; v2(1958.1,822.45) 1961.47,819.08 J10.B5@1984.56,819.08
  Bottom Layer w8: v1(1719.53,860.01) 1790.32,860.01 1827.88,822.45 v2(1958.1,822.45)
